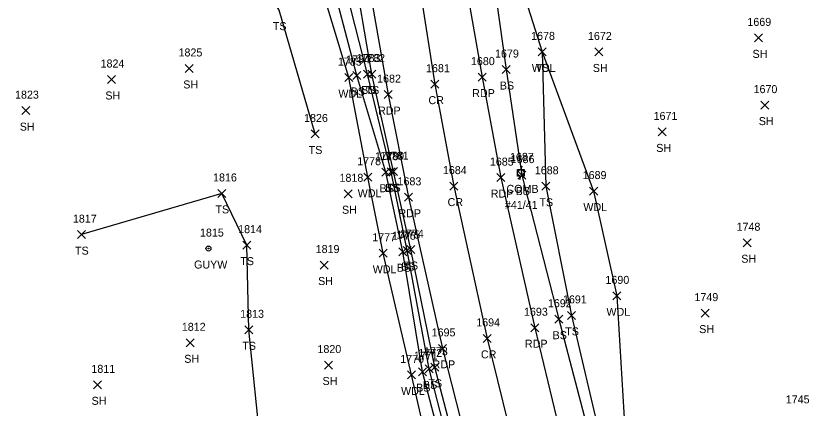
# Model space of a CAD drawing. Extents: x 1885914 to 1887218, y 756253 to 760620.
# Drawn here: x 1886337.1 to 1886535.3, y 759475.9 to 759574 of the extents above; entities that cross this region are included whole.
import ezdxf

# ---------------------------------------------------------------- set-up
doc = ezdxf.new("R2010")
doc.units = 0
for name, color, linetype in [('L_A', 7, 'Continuous'), ('L_I', 7, 'Continuous'), ('L_TIC', 7, 'Continuous'), ('LAWA', 7, 'Continuous'), ('LELB', 7, 'Continuous'), ('P_A', 7, 'Continuous'), ('P_I', 7, 'Continuous'), ('P_TIC', 7, 'Continuous'), ('PET', 7, 'Continuous'), ('PRC', 7, 'Continuous'), ('U_A', 7, 'Continuous'), ('U_C', 7, 'Continuous'), ('U_I', 7, 'Continuous'), ('UP', 7, 'Continuous'), ('UPGW', 7, 'Continuous')]:
    doc.layers.add(name, color=color, linetype=linetype)

msp = doc.modelspace()

# ---------------------------------------------------------------- linework, layer by layer
at = {"layer": 'L_TIC'}
for points in [[(1886521.69, 759567.51), (1886523.69, 759569.51)], [(1886523.69, 759567.51), (1886521.69, 759569.51)], [(1886467.58, 759564.01), (1886469.58, 759566.01)], [(1886469.58, 759564.01), (1886467.58, 759566.01)], [(1886467.58, 759564.01), (1886469.58, 759566.01)], [(1886469.58, 759564.01), (1886467.58, 759566.01)], [(1886481.78, 759563.99), (1886483.78, 759565.99)], [(1886483.78, 759563.99), (1886481.78, 759565.99)], [(1886379.41, 759559.86), (1886381.41, 759561.86)], [(1886381.41, 759559.86), (1886379.41, 759561.86)], [(1886458.57, 759559.59), (1886460.57, 759561.59)], [(1886460.57, 759559.59), (1886458.57, 759561.59)], [(1886419.25, 759557.57), (1886421.25, 759559.57)], [(1886421.25, 759557.57), (1886419.25, 759559.57)], [(1886421.3, 759558.11), (1886423.3, 759560.11)], [(1886423.3, 759558.11), (1886421.3, 759560.11)], [(1886423.93, 759558.47), (1886425.93, 759560.47)], [(1886425.93, 759558.47), (1886423.93, 759560.47)], [(1886425.06, 759558.46), (1886427.06, 759560.46)], [(1886427.06, 759558.46), (1886425.06, 759560.46)], [(1886359.93, 759557.1), (1886361.93, 759559.1)], [(1886361.93, 759557.1), (1886359.93, 759559.1)], [(1886523.26, 759550.69), (1886525.26, 759552.69)], [(1886525.26, 759550.69), (1886523.26, 759552.69)], [(1886338.55, 759549.31), (1886340.55, 759551.31)], [(1886340.55, 759549.31), (1886338.55, 759551.31)], [(1886410.84, 759543.47), (1886412.84, 759545.47)], [(1886412.84, 759543.47), (1886410.84, 759545.47)], [(1886497.62, 759543.99), (1886499.62, 759545.99)], [(1886499.62, 759543.99), (1886497.62, 759545.99)], [(1886428.52, 759533.9), (1886430.52, 759535.9)], [(1886430.52, 759533.9), (1886428.52, 759535.9)], [(1886429.89, 759533.99), (1886431.89, 759535.99)], [(1886431.89, 759533.99), (1886429.89, 759535.99)], [(1886430.42, 759534.05), (1886432.42, 759536.05)], [(1886432.42, 759534.05), (1886430.42, 759536.05)], [(1886424.07, 759532.66), (1886426.07, 759534.66)], [(1886426.07, 759532.66), (1886424.07, 759534.66)], [(1886462.53, 759533.18), (1886464.53, 759535.18)], [(1886464.53, 759533.18), (1886462.53, 759535.18)], [(1886468.5, 759530.39), (1886470.5, 759532.39)], [(1886470.5, 759530.39), (1886468.5, 759532.39)], [(1886387.53, 759528.6), (1886389.53, 759530.6)], [(1886389.53, 759528.6), (1886387.53, 759530.6)], [(1886419.08, 759528.51), (1886421.08, 759530.51)], [(1886421.08, 759528.51), (1886419.08, 759530.51)], [(1886480.47, 759529.19), (1886482.47, 759531.19)], [(1886482.47, 759529.19), (1886480.47, 759531.19)], [(1886352.44, 759518.29), (1886354.44, 759520.29)], [(1886354.44, 759518.29), (1886352.44, 759520.29)], [(1886518.87, 759516.26), (1886520.87, 759518.26)], [(1886520.87, 759516.26), (1886518.87, 759518.26)], [(1886393.75, 759515.66), (1886395.75, 759517.66)], [(1886395.75, 759515.66), (1886393.75, 759517.66)], [(1886432.8, 759514.01), (1886434.8, 759516.01)], [(1886434.8, 759514.01), (1886432.8, 759516.01)], [(1886433.88, 759514.3), (1886435.88, 759516.3)], [(1886435.88, 759514.3), (1886433.88, 759516.3)], [(1886434.76, 759514.56), (1886436.76, 759516.56)], [(1886436.76, 759514.56), (1886434.76, 759516.56)], [(1886427.83, 759513.65), (1886429.83, 759515.65)], [(1886429.83, 759513.65), (1886427.83, 759515.65)], [(1886413.12, 759510.68), (1886415.12, 759512.68)], [(1886415.12, 759510.68), (1886413.12, 759512.68)], [(1886486.24, 759502.98), (1886488.24, 759504.98)], [(1886488.24, 759502.98), (1886486.24, 759504.98)], [(1886474.96, 759498.09), (1886476.96, 759500.09)], [(1886476.96, 759498.09), (1886474.96, 759500.09)], [(1886508.36, 759498.66), (1886510.36, 759500.66)], [(1886510.36, 759498.66), (1886508.36, 759500.66)], [(1886471.77, 759497.14), (1886473.77, 759499.14)], [(1886473.77, 759497.14), (1886471.77, 759499.14)], [(1886394.25, 759494.48), (1886396.25, 759496.48)], [(1886396.25, 759494.48), (1886394.25, 759496.48)], [(1886379.66, 759491.23), (1886381.66, 759493.23)], [(1886381.66, 759491.23), (1886379.66, 759493.23)], [(1886414.22, 759485.67), (1886416.22, 759487.67)], [(1886416.22, 759485.67), (1886414.22, 759487.67)], [(1886437.66, 759484.01), (1886439.66, 759486.01)], [(1886439.66, 759484.01), (1886437.66, 759486.01)], [(1886439.35, 759484.71), (1886441.35, 759486.71)], [(1886441.35, 759484.71), (1886439.35, 759486.71)], [(1886440.76, 759485.12), (1886442.76, 759487.12)], [(1886442.76, 759485.12), (1886440.76, 759487.12)], [(1886434.91, 759483.2), (1886436.91, 759485.2)], [(1886436.91, 759483.2), (1886434.91, 759485.2)], [(1886356.5, 759480.72), (1886358.5, 759482.72)], [(1886358.5, 759480.72), (1886356.5, 759482.72)]]:
    msp.add_lwpolyline(points, dxfattribs=at)
at = {"layer": 'LAWA'}
for points in [[(1886460.31, 759591.25), (1886468.58, 759565.01), (1886481.47, 759530.19), (1886487.24, 759503.98), (1886489.47, 759466.46), (1886499.36, 759440.4), (1886509.45, 759403.39), (1886522.87, 759366.86), (1886528.37, 759345.25)], [(1886474.03, 759328.22), (1886466.13, 759359.95), (1886457.59, 759389.45), (1886449.45, 759426.56), (1886442.01, 759457.6), (1886435.91, 759484.2), (1886428.83, 759514.65), (1886425.07, 759533.66), (1886420.25, 759558.57), (1886411.95, 759586.16)]]:
    msp.add_lwpolyline(points, dxfattribs=at)
at = {"layer": 'LELB'}
for points in [[(1886482.43, 759330.53), (1886473.8, 759362.16), (1886466.41, 759391.35), (1886456.38, 759428.48), (1886448.84, 759459.02), (1886441.76, 759486.12), (1886435.76, 759515.56), (1886431.42, 759535.05), (1886426.06, 759559.46), (1886421.11, 759588.4), (1886418.79, 759606.26), (1886412.24, 759623.91), (1886411.78, 759647.7), (1886414.35, 759668.8), (1886416.75, 759691.58), (1886420.37, 759713.7), (1886423.9, 759735.67), (1886428.12, 759754.98), (1886431.72, 759778.14), (1886436.25, 759795.18), (1886439.73, 759830.38)], [(1886479.66, 759329.52), (1886471.03, 759361.21), (1886461.96, 759390.83), (1886454.24, 759427.83), (1886447.27, 759458.84), (1886440.35, 759485.71), (1886434.88, 759515.3), (1886430.89, 759534.99), (1886424.93, 759559.47), (1886417.7, 759587.99), (1886415.39, 759606.58), (1886409.44, 759622.11), (1886408.97, 759647.11), (1886405.32, 759668.25), (1886398.3, 759701.89), (1886401.43, 759725.45)], [(1886476.45, 759328.91), (1886467.85, 759360.49), (1886459.66, 759390.14), (1886451.87, 759427.06), (1886445.59, 759458.5), (1886438.66, 759485.01), (1886433.8, 759515.01), (1886429.52, 759534.9), (1886422.3, 759559.11), (1886414.83, 759587.35), (1886411.02, 759591.73), (1886403.8, 759605.65), (1886400.43, 759619.74), (1886399.2, 759644.65), (1886399.26, 759666.38)], [(1886411.84, 759544.47), (1886402.87, 759575.45), (1886396.29, 759586.69), (1886391.27, 759620.55), (1886396.39, 759645.17)], [(1886456.79, 759611.09), (1886455.06, 759603.13), (1886455.4, 759590.3), (1886459.57, 759560.59), (1886463.53, 759534.18), (1886472.77, 759498.14), (1886480.93, 759466.98), (1886488.08, 759436.33), (1886497.78, 759399.81), (1886507.53, 759360.15), (1886514.24, 759339.59)], [(1886468.58, 759565.01), (1886469.5, 759531.39), (1886475.96, 759499.09), (1886483.21, 759468.18)], [(1886380.18, 759344.87), (1886380.16, 759374.05), (1886392.15, 759410.77), (1886401.48, 759435.08), (1886395.25, 759495.48), (1886394.75, 759516.66), (1886388.53, 759529.6), (1886353.44, 759519.29)]]:
    msp.add_lwpolyline(points, dxfattribs=at)
at = {"layer": 'P_TIC'}
for points in [[(1886452.63, 759557.69), (1886454.63, 759559.69)], [(1886454.63, 759557.69), (1886452.63, 759559.69)], [(1886440.74, 759555.93), (1886442.74, 759557.93)], [(1886442.74, 759555.93), (1886440.74, 759557.93)], [(1886429.09, 759553.32), (1886431.09, 759555.32)], [(1886431.09, 759553.32), (1886429.09, 759555.32)], [(1886457.27, 759532.55), (1886459.27, 759534.55)], [(1886459.27, 759532.55), (1886457.27, 759534.55)], [(1886445.53, 759530.43), (1886447.53, 759532.43)], [(1886447.53, 759530.43), (1886445.53, 759532.43)], [(1886434.19, 759527.63), (1886436.19, 759529.63)], [(1886436.19, 759527.63), (1886434.19, 759529.63)], [(1886465.8, 759495), (1886467.8, 759497)], [(1886467.8, 759495), (1886465.8, 759497)], [(1886453.86, 759492.34), (1886455.86, 759494.34)], [(1886455.86, 759492.34), (1886453.86, 759494.34)], [(1886442.72, 759489.84), (1886444.72, 759491.84)], [(1886444.72, 759489.84), (1886442.72, 759491.84)]]:
    msp.add_lwpolyline(points, dxfattribs=at)
at = {"layer": 'PET'}
for points in [[(1886505.21, 759975.04), (1886485.32, 759931.76), (1886475.82, 759908.45), (1886466.13, 759882.96), (1886456.93, 759855.61), (1886449.99, 759833.06), (1886442.98, 759808.26), (1886435.87, 759778.49), (1886430.37, 759752.23), (1886424.92, 759721.57), (1886422.03, 759696.27), (1886420.3, 759670.71), (1886419.91, 759641.82), (1886421.23, 759616.47), (1886424.6, 759585.72), (1886430.09, 759554.32), (1886435.19, 759528.63), (1886443.72, 759490.84), (1886451.63, 759459.71), (1886459.13, 759429.12), (1886468.69, 759393.26), (1886479.71, 759351.07), (1886485.06, 759331.17)], [(1886526.14, 759964.92), (1886507.07, 759922.75), (1886498.17, 759900.86), (1886488.16, 759874.15), (1886479.62, 759848.04), (1886473, 759827.05), (1886466.37, 759803.11), (1886458.99, 759773.42), (1886453.36, 759746.97), (1886448.76, 759720.11), (1886445.71, 759693.61), (1886444.44, 759668.96), (1886443.78, 759643.55), (1886445.31, 759617.59), (1886448.26, 759589.04), (1886453.63, 759558.69), (1886458.27, 759533.55), (1886466.8, 759496), (1886474.35, 759464.49), (1886481.64, 759434.54), (1886491.18, 759398.8), (1886502.68, 759358.39), (1886508.23, 759337.95)]]:
    msp.add_lwpolyline(points, dxfattribs=at)
at = {"layer": 'PRC'}
msp.add_lwpolyline([(1886516.05, 759969.43), (1886496.99, 759926.69), (1886487.66, 759904.2), (1886477.68, 759877.96), (1886468.59, 759851.92), (1886461.77, 759829.93), (1886454.6, 759805.62), (1886447.16, 759775.82), (1886441.74, 759748.8), (1886436.89, 759720.56), (1886434.02, 759695.25), (1886432.32, 759669.09), (1886432.26, 759642.82), (1886433.77, 759616.6), (1886436.98, 759587.84), (1886441.74, 759556.93), (1886446.53, 759531.43), (1886454.86, 759493.34), (1886462.57, 759461.76), (1886470.69, 759431.8), (1886480.02, 759395.82), (1886491.53, 759354.96), (1886496.99, 759335.08)], dxfattribs=at)
at = {"layer": 'UP'}
for p, q in [((1886462.46, 759533.91), (1886462.46, 759535.58)), ((1886462.46, 759535.58), (1886464.13, 759535.58)), ((1886463.54, 759536.41), (1886463.29, 759535.58)), ((1886464.13, 759535.58), (1886464.13, 759533.91)), ((1886464.13, 759533.91), (1886462.46, 759533.91)), ((1886463.04, 759533.08), (1886463.29, 759533.91)), ((1886463.29, 759534.74), (1886463.29, 759534.74))]:
    msp.add_line(p, q, dxfattribs=at)
msp.add_circle((1886463.29, 759534.74), 0.833, dxfattribs=at)
at = {"layer": 'UPGW'}
for radius in [0.625, 0.0833]:
    msp.add_circle((1886385.2, 759515.81), radius, dxfattribs=at)

# ---------------------------------------------------------------- texts
at = {"layer": 'L_A'}
for s, p in [('TS', (1886401.28, 759570.45)), ('SH', (1886521.18, 759563.51)), ('WDL', (1886466, 759560.01)), ('TS', (1886466.99, 759560.01)), ('SH', (1886481.26, 759559.99)), ('SH', (1886378.9, 759555.86)), ('BS', (1886458.01, 759555.59)), ('WDL', (1886417.67, 759553.57)), ('BS', (1886420.74, 759554.11)), ('BS', (1886423.37, 759554.47)), ('TS', (1886424.47, 759554.46)), ('SH', (1886359.42, 759553.1)), ('SH', (1886522.74, 759546.69)), ('SH', (1886338.04, 759545.31)), ('TS', (1886410.25, 759539.47)), ('SH', (1886497.11, 759539.99)), ('BS', (1886427.97, 759529.9)), ('BS', (1886429.33, 759529.99)), ('TS', (1886429.83, 759530.05)), ('WDL', (1886422.49, 759528.66)), ('BS', (1886461.97, 759529.18)), ('TS', (1886467.91, 759526.39)), ('TS', (1886386.94, 759524.6)), ('SH', (1886418.57, 759524.51)), ('WDL', (1886478.89, 759525.19)), ('TS', (1886351.85, 759514.29)), ('SH', (1886518.36, 759512.26)), ('TS', (1886393.16, 759511.66)), ('BS', (1886432.24, 759510.01)), ('BS', (1886433.32, 759510.3)), ('TS', (1886434.17, 759510.56)), ('WDL', (1886426.25, 759509.65)), ('SH', (1886412.61, 759506.68)), ('WDL', (1886484.66, 759498.98)), ('TS', (1886474.37, 759494.09)), ('SH', (1886507.85, 759494.66)), ('BS', (1886471.21, 759493.14)), ('TS', (1886393.66, 759490.48)), ('SH', (1886379.15, 759487.23)), ('SH', (1886413.71, 759481.67)), ('BS', (1886437.1, 759480.01)), ('BS', (1886438.79, 759480.71)), ('TS', (1886440.17, 759481.12)), ('WDL', (1886433.33, 759479.2)), ('SH', (1886355.99, 759476.72))]:
    msp.add_text(s, height=2, dxfattribs=at).set_placement(p)
at = {"layer": 'L_I'}
for s, p in [('1669', (1886519.89, 759571.51)), ('1678', (1886465.84, 759568.01)), ('1678', (1886465.84, 759568.01)), ('1672', (1886480.04, 759567.99)), ('1825', (1886377.72, 759563.86)), ('1679', (1886456.82, 759563.59)), ('1785', (1886417.56, 759561.57)), ('1784', (1886419.6, 759562.11)), ('1783', (1886422.24, 759562.47)), ('1782', (1886423.37, 759562.46)), ('1824', (1886358.24, 759561.1)), ('1670', (1886521.43, 759554.69)), ('1823', (1886336.86, 759553.31)), ('1826', (1886409.09, 759547.47)), ('1671', (1886496.45, 759547.99)), ('1779', (1886426.82, 759537.9)), ('1780', (1886428.11, 759537.99)), ('1781', (1886429.29, 759538.05)), ('1778', (1886422.38, 759536.66)), ('1686', (1886460.73, 759537.18)), ('1688', (1886466.76, 759534.39)), ('1816', (1886386.35, 759532.6)), ('1818', (1886417.95, 759532.51)), ('1689', (1886478.72, 759533.19)), ('1817', (1886351.32, 759522.29)), ('1814', (1886392.62, 759519.66)), ('1748', (1886517.18, 759520.26)), ('1776', (1886431.05, 759518.01)), ('1775', (1886432.18, 759518.3)), ('1774', (1886433.06, 759518.56)), ('1777', (1886426.14, 759517.65)), ('1819', (1886411.99, 759514.68)), ('1690', (1886484.42, 759506.98)), ('1691', (1886473.79, 759502.09)), ('1749', (1886506.66, 759502.66)), ('1692', (1886470.03, 759501.14)), ('1813', (1886393.13, 759498.48)), ('1812', (1886378.54, 759495.23)), ('1820', (1886412.44, 759489.67)), ('1771', (1886436.53, 759488.01)), ('1772', (1886437.66, 759488.71)), ('1773', (1886439.07, 759489.12)), ('1770', (1886433.13, 759487.2)), ('1811', (1886355.94, 759484.72)), ('1745', (1886529.48, 759477.08))]:
    msp.add_text(s, height=2, dxfattribs=at).set_placement(p)
at = {"layer": 'P_A'}
for s, p in [('RDP', (1886451.12, 759553.69)), ('CR', (1886440.18, 759551.93)), ('RDP', (1886427.58, 759549.32)), ('RDP', (1886455.76, 759528.55)), ('CR', (1886444.96, 759526.43)), ('RDP', (1886432.68, 759523.63)), ('RDP', (1886464.29, 759491)), ('CR', (1886453.3, 759488.34)), ('RDP', (1886441.21, 759485.84))]:
    msp.add_text(s, height=2, dxfattribs=at).set_placement(p)
at = {"layer": 'P_I'}
for s, p in [('1680', (1886450.8, 759561.69)), ('1681', (1886439.57, 759559.93)), ('1682', (1886427.35, 759557.32)), ('1685', (1886455.53, 759536.55)), ('1684', (1886443.79, 759534.43)), ('1683', (1886432.45, 759531.63)), ('1693', (1886464.06, 759499)), ('1694', (1886452.12, 759496.34)), ('1695', (1886440.98, 759493.84))]:
    msp.add_text(s, height=2, dxfattribs=at).set_placement(p)
at = {"layer": 'U_A'}
for s, p in [('COMB', (1886459.68, 759529.74)), ('GUYW', (1886381.6, 759510.81))]:
    msp.add_text(s, height=2, dxfattribs=at).set_placement(p)
at = {"layer": 'U_C'}
msp.add_text('#41/41', height=2, dxfattribs=at).set_placement((1886459.29, 759525.74))
at = {"layer": 'U_I'}
for s, p in [('1687', (1886460.55, 759537.74)), ('1815', (1886383.08, 759518.81))]:
    msp.add_text(s, height=2, dxfattribs=at).set_placement(p)

doc.saveas('drawing.dxf')
